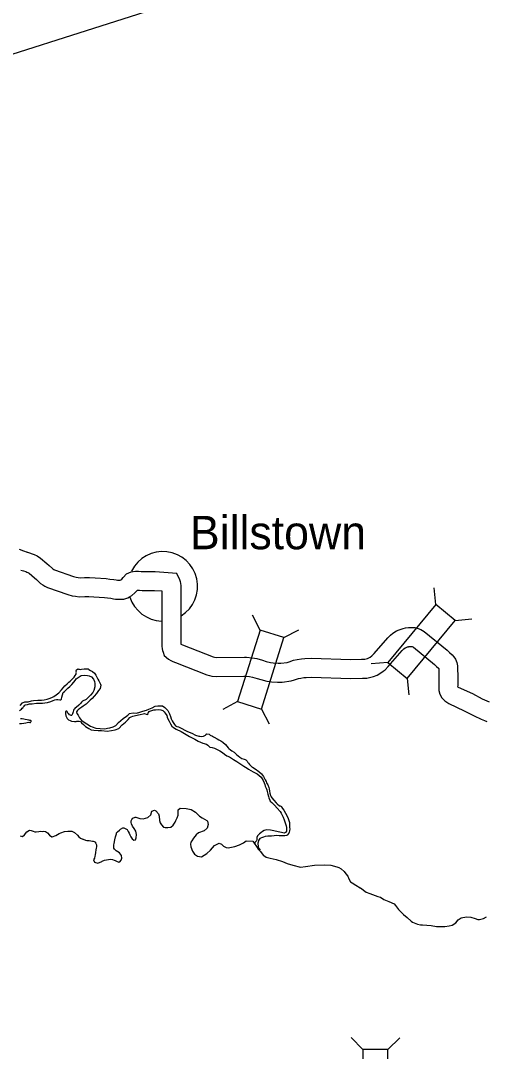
# Model space of a CAD drawing. Extents: x 79818 to 83933, y 50884 to 53307.
# Drawn here: x 81163.3 to 81261.3, y 52890.4 to 53107.7 of the extents above; entities that cross this region are included whole.
import ezdxf

# ---------------------------------------------------------------- set-up
doc = ezdxf.new("R2010")
doc.units = 0
for name, color, linetype in [('Default', 7, 'Continuous'), ('Level 10', 7, 'Continuous'), ('Level 2', 7, 'Continuous'), ('Level 20', 7, 'Continuous'), ('Level 24', 7, 'Continuous'), ('Level 9', 7, 'Continuous')]:
    doc.layers.add(name, color=color, linetype=linetype)

msp = doc.modelspace()

# ---------------------------------------------------------------- linework, layer by layer
at = {"layer": 'Default'}
msp.add_line((81071.88, 53072.06), (81483.45, 53203.33), dxfattribs=at)
at = {"layer": 'Level 10'}
for points in [[(81162.98, 52996.26), (81163.95, 52995.93), (81164.68, 52995.65)], [(81164.55, 52995.69), (81165.21, 52995.49), (81165.73, 52995.31), (81166.16, 52995.15), (81166.78, 52994.86), (81167.49, 52994.4), (81168.84, 52993.27), (81169.36, 52992.81), (81170.02, 52992.16), (81170.12, 52992.1), (81170.29, 52991.99), (81170.45, 52991.92), (81174.47, 52990.52), (81175.03, 52990.37), (81175.46, 52990.3), (81175.85, 52990.25), (81176.77, 52990.27), (81177.81, 52990.3), (81179.06, 52990.19), (81181.33, 52990.06), (81182.11, 52989.97), (81182.93, 52989.85), (81183.46, 52989.77), (81183.75, 52989.73), (81184.19, 52989.7), (81184.33, 52989.7), (81184.44, 52989.77), (81184.63, 52989.93), (81184.94, 52990.26), (81185.66, 52991.04), (81186.61, 52991.52), (81187.5, 52991.66), (81188.17, 52991.63), (81188.72, 52991.58), (81189.18, 52991.54), (81189.67, 52991.53), (81191.67, 52991.58), (81196.22, 52991.23)], [(81163.37, 52991.87), (81163.95, 52991.69), (81164.38, 52991.54), (81164.64, 52991.45), (81164.85, 52991.35), (81165.12, 52991.18), (81166.23, 52990.24), (81166.64, 52989.88), (81167.53, 52989.01), (81167.96, 52988.73), (81168.39, 52988.45), (81169.01, 52988.19), (81173.28, 52986.7), (81174.16, 52986.46), (81174.89, 52986.34), (81175.65, 52986.24), (81176.87, 52986.27), (81177.7, 52986.29), (81178.77, 52986.2), (81180.98, 52986.07), (81181.61, 52986), (81182.35, 52985.9), (81182.89, 52985.81), (81183.33, 52985.75), (81184.01, 52985.7), (81184.58, 52985.69), (81185.09, 52985.74), (81185.93, 52986.01), (81186.3, 52986.22), (81186.76, 52986.49), (81187.42, 52987.04), (81187.88, 52987.55), (81187.95, 52987.63), (81188.38, 52987.59), (81188.96, 52987.55), (81189.67, 52987.53), (81191.57, 52987.57), (81193.12, 52987.45)], [(81196.21, 52991.2), (81196.81, 52989.9), (81196.95, 52989.42), (81197.11, 52988.63), (81197.08, 52986.81), (81197.1, 52978.73), (81197.1, 52976.42), (81197.09, 52976.22), (81197.44, 52976.08), (81203.94, 52973.56), (81204.18, 52973.48), (81204.22, 52973.47), (81204.67, 52973.44), (81210.49, 52973.49), (81210.96, 52973.47), (81212.14, 52973.37), (81213.11, 52973.19), (81214.31, 52972.85), (81215.11, 52972.6), (81216.03, 52972.36), (81216.56, 52972.28), (81217.59, 52972.24), (81218.21, 52972.22), (81219.5, 52972.4), (81219.9, 52972.52), (81220.87, 52972.83), (81221.65, 52973.01), (81222.52, 52973.15), (81223.27, 52973.21), (81224.67, 52973.25), (81232.89, 52972.97), (81235.17, 52973.04), (81235.55, 52973.07), (81235.88, 52973.08), (81236.19, 52973.14), (81236.43, 52973.21), (81236.76, 52973.34), (81237.01, 52973.49), (81237.37, 52973.76), (81237.53, 52973.88), (81237.89, 52974.24), (81240.75, 52977.54), (81241.02, 52977.84), (81241.32, 52978.16), (81241.77, 52978.54), (81242.58, 52979.02), (81243.13, 52979.25), (81243.52, 52979.4), (81244, 52979.56), (81244.49, 52979.66), (81245.11, 52979.75), (81245.75, 52979.78), (81246.41, 52979.72), (81247.1, 52979.54), (81247.7, 52979.31), (81248.43, 52978.92), (81253.23, 52974.94), (81253.71, 52974.48), (81254.32, 52973.97), (81254.62, 52973.59), (81255.04, 52973.06), (81255.32, 52972.38), (81255.43, 52971.67), (81255.46, 52971.35), (81255.49, 52969.23), (81255.47, 52967.49), (81255.46, 52967.26), (81255.59, 52967.17), (81258.57, 52965.8), (81260.66, 52964.72), (81262.09, 52964.06)], [(81193.09, 52987.49), (81193.08, 52986.84), (81193.1, 52978.72), (81193.1, 52976.49), (81193.08, 52975.84), (81193.14, 52975.26), (81193.24, 52974.89), (81193.39, 52974.52), (81193.6, 52973.82), (81194.49, 52973.04), (81194.96, 52972.79), (81195.41, 52972.58), (81195.99, 52972.35), (81202.6, 52969.79), (81203.13, 52969.61), (81203.66, 52969.5), (81204.57, 52969.44), (81210.4, 52969.49), (81210.69, 52969.48), (81211.6, 52969.4), (81212.21, 52969.29), (81213.18, 52969.02), (81213.99, 52968.76), (81215.23, 52968.43), (81216.2, 52968.29), (81217.44, 52968.24), (81218.43, 52968.21), (81220.37, 52968.49), (81221.08, 52968.7), (81221.92, 52968.97), (81222.42, 52969.08), (81223.01, 52969.18), (81223.49, 52969.22), (81224.66, 52969.25), (81232.88, 52968.97), (81235.42, 52969.04), (81235.77, 52969.07), (81236.33, 52969.09), (81237.15, 52969.26), (81237.71, 52969.42), (81238.52, 52969.73), (81239.24, 52970.16), (81239.76, 52970.56), (81240.16, 52970.85), (81240.82, 52971.52), (81243.74, 52974.88), (81243.94, 52975.1), (81244.08, 52975.25), (81244.11, 52975.27), (81244.38, 52975.43), (81244.62, 52975.54), (81244.9, 52975.64), (81245.06, 52975.7), (81245.15, 52975.72), (81245.47, 52975.76), (81245.66, 52975.77), (81245.72, 52975.76), (81245.89, 52975.72), (81246.04, 52975.66), (81246.18, 52975.59), (81250.56, 52971.96), (81251.03, 52971.51), (81251.43, 52971.18), (81251.46, 52971.13), (81251.49, 52969.22), (81251.47, 52967.56), (81251.46, 52967.18), (81251.47, 52966.43), (81251.69, 52965.7), (81252.14, 52964.91), (81252.48, 52964.54), (81252.77, 52964.27), (81253.57, 52963.69), (81256.82, 52962.2), (81258.91, 52961.13), (81260.44, 52960.42), (81261.09, 52960.13), (81261.64, 52959.93)]]:
    msp.add_lwpolyline(points, dxfattribs=at)
at = {"layer": 'Level 2'}
for points in [[(81188.44, 52939.47), (81189.13, 52939.4), (81190.16, 52939.67), (81190.74, 52940.24), (81191.01, 52941), (81191.55, 52941.21), (81191.84, 52941.12), (81192.39, 52940.44), (81192.49, 52939.99), (81192.62, 52939.05), (81192.76, 52938.57), (81193.01, 52938.11), (81193.41, 52937.66), (81193.82, 52937.59), (81194.36, 52937.54), (81195.01, 52937.65), (81195.47, 52938.1), (81195.92, 52938.73), (81196.03, 52939.05), (81196.35, 52939.58), (81196.54, 52940.17), (81196.52, 52940.7), (81196.55, 52941.27), (81196.95, 52941.63), (81198.22, 52941.55), (81199.25, 52941.36), (81200.21, 52940.82), (81201.03, 52939.97), (81201.59, 52939.64), (81202.59, 52939.07), (81202.68, 52938.88), (81202.85, 52938.18), (81202.66, 52937.44), (81202.01, 52936.88), (81200.83, 52936.45), (81200.3, 52936.06), (81199.73, 52935.32), (81199.38, 52934.75), (81199.2, 52934.5), (81199.16, 52934.05), (81199.2, 52933.47), (81199.55, 52932.55), (81199.96, 52931.94), (81200.59, 52931.53), (81201.48, 52931.37), (81202.54, 52932.06), (81203.32, 52932.78), (81204.16, 52933.76), (81205.2, 52934.25), (81205.64, 52934.05), (81206.07, 52933.63), (81206.64, 52933.33), (81207.05, 52933.28), (81208.51, 52933.58), (81209.47, 52933.94), (81210.31, 52934.36), (81210.87, 52934.73), (81212.28, 52934.66), (81212.54, 52934.25), (81213.08, 52933.6), (81213.4, 52933.01), (81213.87, 52932.51), (81214.46, 52931.73), (81214.58, 52931.66), (81215.06, 52931.35), (81215.94, 52931.11), (81217.19, 52930.85), (81218.52, 52930.4), (81219.5, 52930.01), (81220.68, 52929.6), (81222.32, 52929.23), (81223.38, 52929.32), (81225.29, 52929.6), (81227.4, 52929.67), (81228.74, 52929.62), (81229.99, 52929.31), (81230.43, 52929.13), (81230.93, 52928.86), (81231.54, 52928.26), (81231.88, 52927.83), (81232.27, 52927.29), (81232.52, 52926.78), (81232.86, 52926.11), (81233.19, 52925.87), (81233.98, 52925.4), (81234.92, 52924.88), (81234.96, 52924.86), (81236.2, 52923.94), (81236.97, 52923.63), (81238.6, 52923.03), (81239.19, 52922.85), (81239.86, 52922.36), (81240.94, 52921.94), (81242.04, 52921.45), (81242.37, 52921.14), (81242.96, 52920.28), (81244.05, 52919.23), (81244.82, 52918.58), (81245.65, 52917.82), (81245.93, 52917.63), (81246.61, 52917.36)], [(81164.15, 52936.02), (81164.61, 52936.65), (81165.16, 52936.98), (81165.51, 52936.94), (81165.96, 52936.83), (81166.31, 52936.65), (81166.59, 52936.65), (81167.16, 52936.73), (81167.48, 52936.79), (81167.86, 52936.75), (81168.23, 52936.83), (81168.58, 52936.74), (81168.96, 52936.45), (81169.42, 52935.93), (81169.87, 52935.59), (81169.99, 52935.6), (81170.75, 52935.92), (81171.44, 52936.32), (81171.77, 52936.48), (81172.59, 52936.72), (81173.24, 52936.83), (81173.62, 52936.83), (81174.11, 52936.78), (81174.67, 52936.53), (81175.27, 52935.97), (81175.61, 52935.6), (81175.97, 52935.31), (81176.4, 52935.14), (81176.52, 52935.09), (81176.96, 52934.9), (81177.29, 52934.83), (81177.73, 52934.8), (81178.11, 52934.76), (81178.44, 52934.71), (81178.64, 52934.67), (81178.85, 52934.61), (81179.07, 52934.5), (81179.11, 52934.33), (81179.29, 52933.9), (81179.31, 52933.51), (81179.27, 52933.2), (81179.19, 52932.87), (81179.09, 52932.29), (81179.06, 52931.79), (81178.99, 52931.56), (81178.89, 52931.14), (81178.67, 52930.73), (81178.87, 52930.25), (81179.56, 52930.06), (81180.4, 52930.4), (81180.51, 52930.48), (81180.99, 52930.65), (81181.85, 52930.82), (81182.21, 52930.93), (81182.68, 52930.8), (81183.05, 52930.66), (81183.24, 52930.6), (81183.5, 52930.49), (81184.02, 52930.28), (81184.22, 52930.36), (81184.49, 52930.65), (81184.64, 52931.12), (81184.57, 52931.68), (81184.14, 52932.23), (81183.48, 52932.67), (81183.29, 52932.81), (81183.11, 52933), (81182.96, 52933.21), (81182.96, 52933.92), (81183.05, 52934.2), (81183.2, 52934.95), (81183.35, 52935.59), (81183.53, 52936.21), (81183.56, 52936.47), (81183.76, 52936.66), (81184.17, 52937.01), (81184.35, 52937.23), (81184.85, 52937.5), (81185.05, 52937.51), (81185.33, 52937.39), (81185.79, 52937.12), (81186.02, 52936.73), (81186.21, 52936.37), (81186.32, 52936.03), (81186.57, 52935.59), (81186.85, 52935.15), (81187.18, 52934.89), (81187.5, 52934.96), (81187.68, 52935.38), (81187.71, 52936.11), (81187.57, 52936.79), (81187.22, 52937.34), (81186.93, 52937.85), (81186.68, 52938.34), (81186.63, 52938.63), (81186.62, 52938.97), (81186.74, 52939.27), (81186.96, 52939.57), (81187.46, 52939.77), (81187.6, 52939.73), (81188.44, 52939.47)], [(81163.23, 52935.8), (81163.71, 52935.7), (81164.15, 52936.02)], [(81246.61, 52917.36), (81247.01, 52917.21), (81247.61, 52917.06), (81248.02, 52917.03), (81249.84, 52916.9), (81250.99, 52916.69), (81251.85, 52916.68), (81252.74, 52916.69), (81253.65, 52916.81), (81254.33, 52916.95), (81255.08, 52917.49), (81255.56, 52918.13), (81256.19, 52918.51), (81257.32, 52918.72), (81258.21, 52918.65), (81259.17, 52918.35), (81259.68, 52918.2), (81260.09, 52918.2), (81260.94, 52918.38), (81261.54, 52918.74)]]:
    msp.add_lwpolyline(points, dxfattribs=at)
at = {"layer": 'Level 20'}
for p, q in [((81250.85, 52984.59), (81250.52, 52988.1)), ((81213.81, 52979.22), (81212.18, 52982.34)), ((81254.92, 52981.23), (81258.43, 52981.56)), ((81218.84, 52977.64), (81221.97, 52979.26)), ((81240.76, 52972.39), (81237.25, 52972.06)), ((81244.83, 52969.02), (81245.16, 52965.52)), ((81209.06, 52964.11), (81205.94, 52962.48)), ((81214.1, 52962.52), (81215.73, 52959.4)), ((81235.49, 52890.77), (81233.01, 52893.26)), ((81240.77, 52890.75), (81243.27, 52893.23))]:
    msp.add_line(p, q, dxfattribs=at)
for points in [[(81250.85, 52984.59), (81240.76, 52972.39), (81244.83, 52969.02), (81254.92, 52981.23)], [(81214.1, 52962.52), (81218.84, 52977.64), (81213.81, 52979.22), (81209.06, 52964.11)], [(81235.49, 52890.77), (81235.45, 52874.93), (81240.73, 52874.91), (81240.77, 52890.75)]]:
    msp.add_lwpolyline(points, close=True, dxfattribs=at)
at = {"layer": 'Level 24'}
for start, end in [(301.9162, 153.8945), (198.0813, 268.0194)]:
    msp.add_arc((81193.3, 52988.43), 7.33, start, end, dxfattribs=at)
at = {"layer": 'Level 9'}
for points in [[(81163.24, 52963.32), (81163.73, 52963.84), (81164.21, 52964.04), (81164.93, 52964.05), (81165.61, 52964.25), (81166.03, 52964.33), (81166.91, 52964.39), (81167.71, 52964.41), (81168.29, 52964.48), (81168.94, 52964.61), (81169.57, 52964.86), (81170.03, 52965.07), (81170.32, 52965.2), (81170.79, 52965.52), (81171.37, 52966), (81171.9, 52966.6), (81172.27, 52967.03), (81172.66, 52967.43), (81173.11, 52967.86), (81173.47, 52968.2), (81173.75, 52968.46), (81173.97, 52968.66), (81174.6, 52969.3), (81174.8, 52969.61), (81174.99, 52969.94), (81175.05, 52970.22), (81175.06, 52970.34), (81175.03, 52970.44), (81175.02, 52970.58), (81175.04, 52970.68), (81175.09, 52970.83), (81175.4, 52971.01), (81175.49, 52970.97), (81175.65, 52970.93), (81175.88, 52970.91), (81176.13, 52970.94), (81176.73, 52971.04), (81177.56, 52971.03), (81177.7, 52970.91), (81178.04, 52970.65), (81178.47, 52970.46), (81178.91, 52970.12), (81179.18, 52969.69), (81179.62, 52968.85), (81179.83, 52968.53), (81180.04, 52968.11), (81180.15, 52967.78), (81180.2, 52967.57), (81180.08, 52966.91), (81179.74, 52966.44), (81179.28, 52965.84), (81178.82, 52965.25), (81178.38, 52964.77), (81178, 52964.43), (81177.54, 52964), (81177.11, 52963.6), (81176.51, 52963.14), (81176.2, 52962.98), (81175.77, 52962.69), (81175.45, 52962.42), (81175.22, 52962.17), (81175.09, 52961.93), (81175.18, 52961.61), (81175.46, 52961.26), (81175.56, 52960.95), (81175.75, 52960.69), (81176.17, 52960.14), (81176.45, 52959.98), (81176.73, 52959.78), (81177.26, 52959.4), (81178.01, 52958.94), (81178.38, 52958.78), (81179.18, 52958.53), (81180.1, 52958.45), (81181.05, 52958.35), (81181.65, 52958.5), (81182.11, 52958.57), (81182.83, 52958.81), (81183.37, 52959.1), (81183.94, 52959.7), (81184.47, 52960.13), (81184.95, 52960.53), (81185.66, 52961.07), (81185.94, 52961.24), (81186.29, 52961.62), (81187.04, 52961.73), (81187.76, 52961.7), (81188.45, 52961.91), (81189.08, 52962.08), (81189.85, 52962.35), (81190.36, 52962.53), (81191.05, 52962.82), (81191.69, 52963.13), (81192.21, 52963.25), (81193.2, 52963.24), (81193.73, 52962.86), (81194.32, 52962.27), (81194.7, 52961.57), (81194.88, 52960.96), (81195.05, 52960.46), (81195.25, 52960.05)], [(81163.1, 52962.16), (81163.32, 52962.36), (81163.47, 52962.51), (81163.65, 52962.73), (81163.83, 52962.89), (81163.88, 52962.97), (81164.03, 52963.17), (81164.18, 52963.37), (81164.33, 52963.47), (81164.74, 52963.52), (81165.21, 52963.65), (81165.73, 52963.67), (81166.67, 52963.76), (81167.35, 52963.76), (81167.94, 52963.81), (81168.44, 52963.86), (81168.95, 52963.92), (81169.66, 52964.16), (81170.14, 52964.33), (81170.51, 52964.49), (81170.91, 52964.58), (81171.19, 52964.57), (81171.56, 52964.47), (81171.78, 52964.47), (81171.94, 52964.66), (81172.03, 52965.05), (81172.31, 52966.01), (81172.54, 52966.26), (81172.92, 52966.57), (81173.26, 52966.93), (81173.66, 52967.34), (81174.09, 52967.73), (81174.55, 52968.19), (81174.78, 52968.54), (81175.05, 52968.89), (81175.41, 52969.22), (81176.07, 52969.6), (81176.79, 52969.71), (81177.38, 52969.65), (81177.78, 52969.54), (81178.23, 52969.36), (81178.7, 52968.87), (81178.9, 52968.34), (81178.95, 52967.93), (81178.96, 52967.27), (81178.75, 52966.47), (81178.56, 52966.07), (81178.06, 52965.51), (81177.65, 52965.07), (81177.4, 52964.82), (81177.13, 52964.55), (81176.87, 52964.41), (81176.61, 52964.34), (81176.33, 52964.22), (81176.16, 52963.98), (81175.91, 52963.72), (81175.59, 52963.36), (81175.01, 52962.88)], [(81175.01, 52962.88), (81174.78, 52962.82), (81174.64, 52962.62), (81174.53, 52962.45), (81174.47, 52962.22), (81174.39, 52961.94), (81174.28, 52961.57), (81174.21, 52961.38), (81174.13, 52961.28), (81174.07, 52961.21), (81173.97, 52961.22), (81173.8, 52961.25), (81173.65, 52961.33), (81173.48, 52961.52), (81173.37, 52961.59), (81173.28, 52961.71), (81173.23, 52961.86), (81173.1, 52962.06), (81173.07, 52962.07), (81172.9, 52962.13), (81172.8, 52962.02), (81172.79, 52961.88), (81172.75, 52961.63), (81172.85, 52961.11), (81173.02, 52960.69), (81173.14, 52960.53), (81173.43, 52960.28), (81173.73, 52960.11), (81174.06, 52960), (81174.69, 52959.93), (81174.99, 52959.95), (81175.15, 52959.99), (81175.41, 52959.98), (81175.66, 52960.01), (81175.93, 52959.9), (81176.18, 52959.61), (81176.59, 52959.3), (81176.98, 52958.87), (81177.67, 52958.42), (81178.18, 52958.15), (81178.74, 52958.07), (81179.67, 52958.01), (81180.34, 52958.02), (81181.53, 52957.89), (81182.49, 52958.05), (81183.24, 52958.17), (81184.04, 52958.44), (81184.74, 52959.19), (81185.41, 52959.76), (81185.66, 52960.03), (81185.99, 52960.37), (81186.36, 52960.75), (81186.62, 52960.91), (81187, 52961.06), (81187.53, 52961.21), (81188.54, 52961.39), (81189.13, 52961.56), (81189.46, 52961.6), (81189.77, 52961.48), (81190.05, 52961.4), (81190.18, 52961.54), (81190.14, 52961.66), (81190.24, 52961.85), (81190.4, 52962), (81190.59, 52962.09), (81191.39, 52962.39), (81191.75, 52962.42), (81192.39, 52962.48), (81192.87, 52962.37), (81193.33, 52962.24), (81193.58, 52961.99), (81193.8, 52961.69), (81194.16, 52961.2), (81194.24, 52960.87), (81194.37, 52960.49), (81194.64, 52959.97), (81194.91, 52959.45), (81195.19, 52958.94), (81195.52, 52958.64), (81196.09, 52958.32), (81197.15, 52957.8), (81197.84, 52957.42), (81198.94, 52956.74), (81200.01, 52956.17), (81200.73, 52955.75), (81201.7, 52955.36), (81202.51, 52955.17), (81202.79, 52954.9), (81202.9, 52954.76), (81203.19, 52954.51), (81203.69, 52954.45), (81204.18, 52954.31), (81205.06, 52953.91), (81205.32, 52953.71), (81205.87, 52953.38), (81206.31, 52953.06), (81206.77, 52952.72), (81207.32, 52952.47), (81207.8, 52952.22), (81208.21, 52951.93), (81208.92, 52951.48)], [(81163.07, 52959.5), (81163.49, 52959.48), (81164.01, 52959.55), (81164.38, 52959.65), (81164.69, 52959.73), (81165.02, 52959.76), (81165.25, 52959.7), (81165.4, 52959.73), (81165.49, 52959.83), (81165.53, 52959.95), (81165.55, 52960.09), (81165.47, 52960.13), (81165.28, 52960.17), (81165.13, 52960.18), (81164.97, 52960.2), (81164.67, 52960.29), (81164.29, 52960.37), (81164, 52960.43), (81163.65, 52960.47), (81163.31, 52960.47)], [(81195.25, 52960.05), (81195.44, 52959.71), (81195.73, 52959.28), (81195.95, 52959.03), (81196.24, 52958.84), (81196.59, 52958.77), (81197.28, 52958.46), (81197.96, 52958.12), (81198.52, 52957.85), (81199.4, 52957.46), (81200.17, 52957.05), (81200.91, 52956.85), (81201.11, 52956.82), (81201.44, 52956.76), (81201.87, 52956.82), (81202.29, 52957.03), (81202.35, 52957.11), (81202.42, 52957.21), (81202.46, 52957.24), (81202.55, 52957.32), (81203.04, 52957.25), (81203.31, 52957.01), (81203.75, 52956.81), (81203.99, 52956.71), (81204.13, 52956.63), (81204.73, 52956.28), (81205.1, 52956.06), (81205.5, 52955.86), (81205.92, 52955.6), (81206.48, 52955.07), (81206.79, 52954.73), (81207.04, 52954.35), (81207.19, 52954.23), (81207.53, 52953.94), (81207.86, 52953.75), (81208.37, 52953.44), (81208.85, 52952.95), (81209.15, 52952.67), (81209.52, 52952.37), (81209.72, 52952.25), (81209.98, 52952.14), (81210.44, 52951.96), (81210.63, 52951.9), (81210.83, 52951.82), (81210.96, 52951.7), (81211.07, 52951.56), (81211.23, 52951.28), (81211.35, 52951.12), (81211.55, 52950.85), (81212.05, 52950.38), (81212.21, 52950.3), (81212.74, 52949.95), (81213.55, 52949.41), (81214.13, 52948.89), (81214.52, 52948.32), (81214.89, 52947.64), (81215.08, 52947.25), (81215.18, 52946.98), (81215.42, 52946.58), (81215.68, 52946.03), (81215.71, 52945.73), (81215.79, 52945.25), (81215.89, 52944.8), (81215.99, 52944.29), (81216.11, 52944.03), (81216.28, 52943.8), (81216.72, 52943.35), (81217.19, 52942.77), (81217.43, 52942.54), (81217.9, 52942.14), (81218.05, 52942.14), (81218.29, 52941.97), (81218.37, 52941.81), (81218.54, 52941.6), (81218.81, 52941.2), (81219.16, 52940.59), (81219.48, 52939.93), (81219.72, 52939.45), (81220.02, 52938.66), (81220.03, 52937.6), (81220.08, 52937.31), (81220.02, 52936.89), (81219.93, 52936.6), (81219.83, 52936.39), (81219.51, 52935.93), (81219.39, 52935.88), (81219, 52935.81), (81218.71, 52935.79), (81218.16, 52935.79), (81217.86, 52935.83), (81217.22, 52935.89), (81216.75, 52935.84), (81216.22, 52935.78), (81215.47, 52935.77), (81214.84, 52935.66), (81214.52, 52935.54), (81214.11, 52935.36), (81213.77, 52935.23), (81213.58, 52935.04), (81213.45, 52934.83), (81213.39, 52934.49)], [(81208.92, 52951.48), (81209.33, 52951.2), (81209.72, 52950.94), (81210.38, 52950.48), (81211.07, 52950.05), (81211.37, 52949.86), (81212.31, 52949.28), (81212.62, 52949.2), (81213.07, 52948.98), (81213.22, 52948.9), (81214, 52948.18), (81214.46, 52947.45), (81214.65, 52946.96), (81214.77, 52946.62), (81214.87, 52946.3), (81215.06, 52945.88), (81215.19, 52945.51), (81215.28, 52945.15), (81215.42, 52944.62), (81215.58, 52944.13), (81215.64, 52943.86), (81215.85, 52943.36), (81215.96, 52943.15), (81216.25, 52942.84), (81216.62, 52942.46), (81216.86, 52942.25), (81217.38, 52941.63), (81218.02, 52940.94), (81218.22, 52940.62), (81218.69, 52939.74), (81218.86, 52939.21), (81219.01, 52938.77), (81219.16, 52938.34), (81219.29, 52937.9), (81219.36, 52937.55), (81219.36, 52937.08), (81219.38, 52936.9), (81219.37, 52936.82), (81219.23, 52936.56), (81219.18, 52936.5), (81218.88, 52936.39), (81218.31, 52936.51), (81217.63, 52936.66), (81216.73, 52936.88), (81215.99, 52937.02), (81215.23, 52937.05), (81214.64, 52936.93), (81214.29, 52936.73), (81213.97, 52936.48), (81213.71, 52936.23), (81213.48, 52936.02), (81213.23, 52935.79), (81213.12, 52935.46), (81213.12, 52935.01), (81213.03, 52934.77), (81212.86, 52934.56), (81212.71, 52934.39), (81212.68, 52934.2), (81212.68, 52934.17)], [(81213.39, 52934.49), (81213.36, 52934.26), (81213.34, 52934.05), (81213.39, 52933.73), (81213.43, 52933.53), (81213.57, 52933.13), (81213.8, 52932.78)]]:
    msp.add_lwpolyline(points, dxfattribs=at)

# ---------------------------------------------------------------- texts
at = {"layer": 'Level 24'}
msp.add_text('Billstown', height=7.04, dxfattribs=at).set_placement((81199, 52996.25))

doc.saveas('drawing.dxf')
